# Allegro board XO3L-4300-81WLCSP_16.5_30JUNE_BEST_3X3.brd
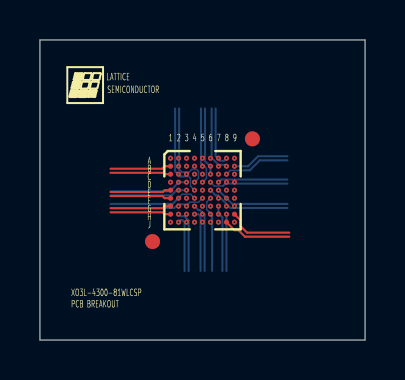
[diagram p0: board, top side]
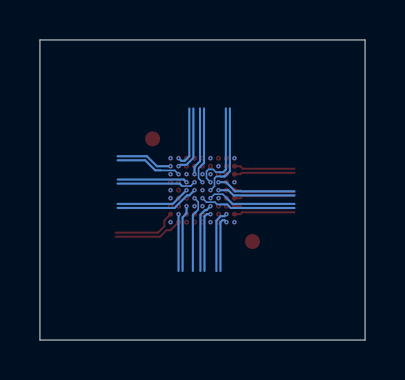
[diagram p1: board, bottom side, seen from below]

Outline 16.28 x 15.02 mm; copper layers: TOP, L2_SIG, L3_PWR/GND, BOTTOM. Coordinates in mm from the lower left corner of the outline.
Outline path: 0,15.02 0,0 16.28,0 16.28,15.02 0,15.02

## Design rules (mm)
net group PB4: nets PB4A PB4B
net group PB7: nets PB7A PB7B
net group PB9: nets PB9A PB9B
net group PB13: nets PB13A PB13B
net group PB15: nets PB15A PB15B
net group PB20: nets PB20A PB20B
net group PB23: nets PB23A PB23B
net group PB24: nets PB24A PB24B
net group PB27: nets PB27A PB27B
net group PB30: nets PB30A PB30B
net group PL4: nets PL4A PL4B
net group PL7: nets PL7A PL7B
net group PL8: nets PL8C PL8D
net group PL15: nets PL15A PL15B
net group PL17: nets PL17A PL17B
net group PL18: nets PL18A PL18B
net group PT9: nets PT9A PT9B
net group PT10: nets PT10A PT10B
net group PT11: nets PT11A PT11B
net group PT13: nets PT13C PT13D
net group PT15: nets PT15C PT15D
net group PT18: nets PT18A PT18B
net group PT19: nets PT19A PT19B
net group PT20: nets PT20C PT20D
net group PT21: nets PT21A PT21B
net group PT22: nets PT22A PT22B
net group PT23: nets PT23C PT23D
net group PT24: nets PT24A PT24B
net group PT25: nets PT25A PT25B
net group PT27: nets PT27A PT27B
net group PT28: nets PT28C PT28D

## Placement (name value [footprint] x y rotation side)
BGA  -  [BGA81N40P9X9_379X369X57B26N]  8.14 7.5 270 top
NOREF  -  []  1.09 11.54 0 top

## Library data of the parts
BGA = BGA81N40P9X9_379X369X57B26N

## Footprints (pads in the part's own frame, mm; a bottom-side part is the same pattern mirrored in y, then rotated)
BGA81N40P9X9_379X369X57B26N
  round 0.75 smd: (-2.57,2.5) (2.57,-2.5)
  round 0.254 smd: A1(-1.6,-1.6) A2(-1.6,-1.2) A3(-1.6,-0.8) A4(-1.6,-0.4) A5(-1.6,0) A6(-1.6,0.4) A7(-1.6,0.8) A8(-1.6,1.2) A9(-1.6,1.6) B1(-1.2,-1.6) B2(-1.2,-1.2) B3(-1.2,-0.8) B4(-1.2,-0.4) B5(-1.2,0) B6(-1.2,0.4) B7(-1.2,0.8) B8(-1.2,1.2) B9(-1.2,1.6) C1(-0.8,-1.6) C2(-0.8,-1.2) C3(-0.8,-0.8) C4(-0.8,-0.4) C5(-0.8,0) C6(-0.8,0.4) C7(-0.8,0.8) C8(-0.8,1.2) C9(-0.8,1.6) D1(-0.4,-1.6) D2(-0.4,-1.2) D3(-0.4,-0.8) D4(-0.4,-0.4) D5(-0.4,0) D6(-0.4,0.4) D7(-0.4,0.8) D8(-0.4,1.2) D9(-0.4,1.6) E1(0,-1.6) E2(0,-1.2) E3(0,-0.8) E4(0,-0.4) E5(0,0) E6(0,0.4) E7(0,0.8) E8(0,1.2) E9(0,1.6) F1(0.4,-1.6) F2(0.4,-1.2) F3(0.4,-0.8) F4(0.4,-0.4) F5(0.4,0) F6(0.4,0.4) F7(0.4,0.8) F8(0.4,1.2) F9(0.4,1.6) G1(0.8,-1.6) G2(0.8,-1.2) G3(0.8,-0.8) G4(0.8,-0.4) G5(0.8,0) G6(0.8,0.4) G7(0.8,0.8) G8(0.8,1.2) G9(0.8,1.6) H1(1.2,-1.6) H2(1.2,-1.2) H3(1.2,-0.8) H4(1.2,-0.4) H5(1.2,0) H6(1.2,0.4) H7(1.2,0.8) H8(1.2,1.2) H9(1.2,1.6) J1(1.6,-1.6) J2(1.6,-1.2) J3(1.6,-0.8) J4(1.6,-0.4) J5(1.6,0) J6(1.6,0.4) J7(1.6,0.8) J8(1.6,1.2) J9(1.6,1.6)

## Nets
GND: BGA.A1 BGA.A9 BGA.E5 BGA.G5 BGA.J1 BGA.J9
VCC: BGA.C4 BGA.D1 BGA.E9 BGA.F3
VCCIO0: BGA.A4 BGA.C5 BGA.C7
VCCIO2: BGA.G6 BGA.J4
VCCIO3: BGA.F9
VCCIO5: BGA.C9
PB4A: BGA.H9
PB4B: BGA.J8
PB7A: BGA.H8
PB7B: BGA.G7
PB9A: BGA.H7
PB9B: BGA.J7
PB13A: BGA.J6
PB13B: BGA.H6
PB15A: BGA.H5
PB15B: BGA.J5
PB20A: BGA.G4
PB20B: BGA.H4
PB23A: BGA.G3
PB23B: BGA.G2
PB24A: BGA.H3
PB24B: BGA.J3
PB27A: BGA.H2
PB27B: BGA.J2
PB30A: BGA.G1
PB30B: BGA.H1
PL4A: BGA.B9
PL4B: BGA.C8
PL5A: BGA.D8
PL7A: BGA.E6
PL7B: BGA.E7
PL8C: BGA.D9
PL8D: BGA.E8
PL15A: BGA.F8
PL15B: BGA.F7
PL16A: BGA.F6
PL17A: BGA.G9
PL17B: BGA.G8
PL18A: BGA.F5
PL18B: BGA.F4
PT9A: BGA.D7
PT9B: BGA.D6
PT10A: BGA.D5
PT10B: BGA.C6
PT11A: BGA.A8
PT11B: BGA.B8
PT13C: BGA.B7
PT13D: BGA.A7
PT15C: BGA.E4
PT15D: BGA.D4
PT18A: BGA.A6
PT18B: BGA.B6
PT19A: BGA.E3
PT19B: BGA.D3
PT20C: BGA.A5
PT20D: BGA.B5
PT21A: BGA.C3
PT21B: BGA.B4
PT22A: BGA.F2
PT22B: BGA.E2
PT23C: BGA.D2
PT23D: BGA.C2
PT24A: BGA.B3
PT24B: BGA.A3
PT25A: BGA.F1
PT25B: BGA.E1
PT27A: BGA.A2
PT27B: BGA.B2
PT28C: BGA.C1
PT28D: BGA.B1

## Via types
v1: diameter 0.2, hole 0.1, TOP to L2_SIG, 32 vias
v2: diameter 0.203, hole 0.102, TOP to BOTTOM, 41 vias

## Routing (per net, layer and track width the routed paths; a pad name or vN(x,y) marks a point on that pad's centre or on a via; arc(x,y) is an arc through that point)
GND:
  vias: v2(6.54,9.1) v2(6.54,5.9) v2(8.14,7.5) v2(8.14,6.7) v2(9.74,9.1) v2(9.74,5.9)
VCC:
  vias: v2(6.54,7.9) v2(7.34,7.1) v2(7.74,8.3) v2(9.74,7.5)
VCCIO0:
  vias: v2(7.74,9.1) v2(8.14,8.3) v2(8.94,8.3)
VCCIO2:
  vias: v2(7.74,5.9) v2(8.54,6.7)
VCCIO3:
  vias: v2(9.74,7.1)
VCCIO5:
  vias: v2(9.74,8.3)
PB4A: length 3.3
  TOP w0.102: BGA.H9 10.05,5.99 10.05,5.69 10.37,5.38 12.49,5.38
PB4B: length 3.4
  TOP w0.102: BGA.J8 9.74,5.5 9.94,5.5 10.26,5.17 12.49,5.17
PB7A: length 2.8
  BOTTOM w0.102: v2(9.34,6.3) 9.34,3.46
PB7B: length 3.3
  BOTTOM w0.102: v2(8.94,6.7) 8.94,6.34 9.14,6.14 9.14,3.46
PB9A: length 3.2
  L2_SIG w0.076: 9.25,5.98 9.14,6.09 9.14,6.1 v1(8.94,6.3)
  L2_SIG w0.102: 9.25,5.98 9.77,5.47 9.77,3.46
PB9B: length 2.7
  L2_SIG w0.102: 9.56,3.46 9.56,5.28 v1(8.94,5.9)
PB13A: length 2.6
  L2_SIG w0.102: 8.87,3.46 8.87,5.14 8.54,5.47 v1(8.54,5.9)
PB13B: length 3.1
  L2_SIG w0.076: v1(8.54,6.3) 8.74,6.1 8.74,5.99 8.74,5.98 8.74,5.72
  L2_SIG w0.102: 9.08,3.46 9.08,5.23 8.74,5.56 8.74,5.72
PB15A: length 2.9
  L2_SIG w0.076: v1(8.14,6.3) 8.34,6.1 8.34,5.49
  L2_SIG w0.102: 8.34,3.46 8.34,5.49
PB15B: length 2.4
  L2_SIG w0.102: v1(8.14,5.9) 8.14,5.58 8.14,5.58 8.14,3.46
PB20A: length 3.5
  BOTTOM w0.102: 8.24,3.46 8.24,6.27 8.01,6.5 7.94,6.5 v2(7.74,6.7)
PB20B: length 3.1
  BOTTOM w0.102: 8.04,3.46 8.04,6.19 7.93,6.3 v2(7.74,6.3)
PB23A: length 4.1
  L2_SIG w0.076: v1(7.34,6.7) 7.14,6.9 6.6,6.9 6.59,6.9 6.52,6.9
  L2_SIG w0.102: 3.54,6.36 5.98,6.36 6.52,6.9
PB23B: length 3.6
  L2_SIG w0.102: v1(6.94,6.7) 6.68,6.7 6.14,6.16 3.54,6.16
PB24A: length 2.9
  L2_SIG w0.076: v1(7.34,6.3) 7.14,6.1 7.14,5.99 7.14,5.98 7.14,5.75
  L2_SIG w0.102: 7.14,3.48 7.14,5.75
PB24B: length 2.4
  L2_SIG w0.102: 7.34,3.48 v1(7.34,5.9)
PB27A: length 3.2
  BOTTOM w0.102: 7.44,3.45 7.44,5.98 7.22,6.2 7.04,6.2 v2(6.94,6.3)
PB27B: length 2.8
  BOTTOM w0.102: 7.24,3.45 7.24,5.9 7.14,6 7.04,6 v2(6.94,5.9)
PB30A: length 3
  TOP w0.102: BGA.G1 6.25,6.7 6.14,6.6 3.54,6.6
PB30B: length 3
  TOP w0.102: BGA.H1 6.25,6.3 6.15,6.39 3.54,6.39
PL4A: length 2.9
  BOTTOM w0.102: v2(9.74,8.7) 10.42,8.7 10.92,9.2 12.39,9.2
PL4B: length 3.3
  BOTTOM w0.076: 10.25,8.5 10.25,8.49 9.53,8.49 v2(9.34,8.3)
  BOTTOM w0.102: 12.39,9 11.01,9 10.51,8.5 10.25,8.5 ; v2(9.34,8.3) 9.34,8.3
PL5A: length 3.1
  L2_SIG w0.076: 12.39,8.1 9.54,8.1 v1(9.34,7.9)
PL7A: length 4.2
  BOTTOM w0.102: 12.39,6.61 9.54,6.61 8.91,7.24 8.8,7.24 v2(8.54,7.5)
PL7B: length 3.7
  BOTTOM w0.102: 12.39,6.81 9.63,6.81 v2(8.94,7.5)
PL8C: length 2.7
  L2_SIG w0.102: 12.39,7.7 10.38,7.7 10.18,7.9 v1(9.74,7.9)
PL8D: length 3.2
  L2_SIG w0.076: 10.16,7.62 10.07,7.7 9.54,7.7 v1(9.34,7.5)
  L2_SIG w0.102: 10.16,7.62 10.27,7.5 12.39,7.5
PL15A: length 3.2
  L2_SIG w0.076: v1(9.34,7.1) 9.35,7.1 9.54,6.91 9.94,6.91
  L2_SIG w0.102: 9.94,6.91 10.02,6.99 12.39,6.99
PL15B: length 3.6
  L2_SIG w0.076: 9.99,7.3 9.14,7.3 v1(8.94,7.1)
  L2_SIG w0.102: 12.39,7.21 10.09,7.21 9.99,7.3
PL16A: length 3.8
  BOTTOM w0.076: 8.47,6.41 8.35,6.53 8.35,6.91 v2(8.54,7.1)
  BOTTOM w0.102: 8.62,3.46 8.62,6.26 8.47,6.41
PL17A: length 2.8
  L2_SIG w0.102: v1(9.74,6.7) 10.21,6.23 12.39,6.23
PL17B: length 3.3
  L2_SIG w0.102: 12.39,6.03 10.13,6.03 9.77,6.38 9.66,6.38 v1(9.34,6.7)
PL18A: length 4.8
  BOTTOM w0.076: v2(8.14,7.1) 7.94,6.9 7.52,6.9 7.4,6.79 7.25,6.79
  BOTTOM w0.102: 3.54,6.61 6.73,6.61 6.9,6.79 7.25,6.79
PL18B: length 4.5
  BOTTOM w0.076: v2(7.74,7.1) 7.54,7.3 7.13,7.3 6.97,7.14
  BOTTOM w0.102: 6.97,7.14 6.64,6.81 3.54,6.81
PT9A: length 3.5
  BOTTOM w0.102: 12.38,8.03 9.07,8.03 v2(8.94,7.9)
PT9B: length 4
  BOTTOM w0.076: 9.19,7.74 9.16,7.71 8.73,7.71 v2(8.54,7.9)
  BOTTOM w0.102: 12.39,7.83 9.28,7.83 9.19,7.74
PT10A: length 3.9
  BOTTOM w0.076: 8.28,8.65 8.34,8.59 8.34,8.1 v2(8.14,7.9)
  BOTTOM w0.102: 8.06,11.59 8.06,8.86 8.28,8.65
PT10B: length 3.4
  BOTTOM w0.102: 8.27,11.59 8.27,8.95 8.54,8.67 8.54,8.39 8.54,8.39 v2(8.54,8.3)
PT11A: length 3.1
  BOTTOM w0.102: 8.8,11.59 8.8,9.2 9.03,8.97 9.21,8.97 v2(9.34,9.1)
PT11B: length 3.4
  BOTTOM w0.102: 8.6,11.59 8.6,9.12 8.94,8.77 9.27,8.77 v2(9.34,8.7)
PT13C: length 3.2
  L2_SIG w0.076: v1(8.94,8.7) 9.14,8.9 9.14,9.31 9.26,9.43
  L2_SIG w0.102: 9.64,11.59 9.64,9.81 9.26,9.43
PT13D: length 2.7
  L2_SIG w0.102: v1(8.94,9.1) 8.94,9.39 9.44,9.89 9.44,11.59
PT15C: length 4.7
  BOTTOM w0.076: v2(7.74,7.5) 7.54,7.7 7.54,8.09 7.45,8.19 7.23,8.19
  BOTTOM w0.102: 6.77,11.59 6.77,8.45 7.02,8.2 7.04,8.2 7.05,8.19 7.23,8.19
PT15D: length 4.8
  BOTTOM w0.076: 7.29,8.4 7.47,8.4 7.61,8.54 7.84,8.54 7.94,8.44 7.94,8.1 v2(7.74,7.9)
  BOTTOM w0.102: 6.97,11.59 6.97,8.53 7.1,8.4 7.29,8.4
PT18A: length 2.7
  L2_SIG w0.076: 8.67,9.86 8.54,9.74 v1(8.54,9.1)
  L2_SIG w0.102: 8.67,9.86 8.94,10.14 8.94,11.59
PT18B: length 3.1
  L2_SIG w0.076: 8.83,9.74 8.74,9.65 8.74,8.9 v1(8.54,8.7)
  L2_SIG w0.102: 9.14,11.59 9.14,10.05 8.83,9.74
PT19A: length 3.9
  BOTTOM w0.102: v2(7.34,7.5) 6.84,7.5 6.59,7.24 3.54,7.24
PT19B: length 4
  BOTTOM w0.102: v2(7.34,7.9) 6.96,7.9 6.5,7.44 3.54,7.44
PT20C: length 2.6
  L2_SIG w0.102: v1(8.14,9.1) 8.14,9.68 7.99,9.84 7.99,11.59
PT20D: length 3
  L2_SIG w0.076: 8.23,9.88 8.34,9.77 8.34,9.02 8.34,9.01 8.34,8.9 v1(8.14,8.7)
  L2_SIG w0.102: 8.23,9.88 8.19,9.92 8.19,11.59
PT21A: length 3.4
  L2_SIG w0.076: 7.43,9.81 7.54,9.71 7.54,8.5 v1(7.34,8.3)
  L2_SIG w0.102: 7.43,9.81 7.35,9.89 7.35,11.59
PT21B: length 3.1
  L2_SIG w0.076: 7.85,9.38 7.94,9.29 7.94,8.9 v1(7.74,8.7)
  L2_SIG w0.102: 7.56,11.59 7.56,9.99 7.74,9.8 7.74,9.49 7.85,9.38
PT22A: length 3.5
  L2_SIG w0.102: 3.54,7.22 6.82,7.22 v1(6.94,7.1)
PT22B: length 3.4
  L2_SIG w0.102: v1(6.94,7.5) 6.86,7.42 3.54,7.42
PT23C: length 3.6
  L2_SIG w0.102: 3.54,8.3 6.48,8.3 6.69,8.08 6.76,8.08 v1(6.94,7.9)
PT23D: length 3.5
  L2_SIG w0.102: 3.54,8.5 6.59,8.5 6.79,8.3 v1(6.94,8.3)
PT24A: length 3.2
  L2_SIG w0.076: 6.87,9.54 7.15,9.26 7.15,8.89 v2(7.34,8.7)
  L2_SIG w0.102: 6.67,11.59 6.67,9.75 6.87,9.54
PT24B: length 2.7
  L2_SIG w0.076: 7.01,9.69 7.03,9.67 7.03,9.67 7.33,9.38 7.33,9.11 v1(7.34,9.1)
  L2_SIG w0.102: 6.87,11.59 6.87,9.83 7.01,9.69
PT25A: length 3
  TOP w0.102: 3.54,7.21 6.14,7.21 6.25,7.1 BGA.F1
PT25B: length 3
  TOP w0.102: BGA.E1 6.25,7.5 6.16,7.41 3.54,7.41
PT27A: length 3.7
  L2_SIG w0.102: 3.54,9.79 5.94,9.79 6.33,9.4 6.64,9.4 v1(6.94,9.1)
PT27B: length 3.8
  L2_SIG w0.102: 3.54,9.58 5.86,9.58 6.23,9.21 6.23,9.07 6.46,8.85 6.79,8.85 v1(6.94,8.7)
PT28C: length 3
  TOP w0.102: 3.54,8.37 6.18,8.37 6.25,8.3 BGA.C1
PT28D: length 3.1
  TOP w0.102: BGA.B1 6.25,8.7 6.12,8.57 3.54,8.57

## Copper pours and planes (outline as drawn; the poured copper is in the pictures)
GND on L3_PWR/GND: 8.39,6.95 8.24,6.8 8.24,6.35 8.09,6.2 7.39,6.2 7.24,6.05 7.24,5.5 6.14,5.5 6.14,9.5 10.25,9.5 10.25,8.2 9.24,8.2 9.24,8.56 8.5,9.3 7.63,9.3 7.48,9.15 7.48,8.55 6.64,8.55 6.34,8.25 6.34,7.22 6.69,6.87 7.43,6.87 7.63,7.07 7.63,7.44 7.79,7.6 9.16,7.6 9.51,7.25 9.51,6.54 10.25,6.54 10.25,5.5 9.04,5.5 9.04,6.8 8.89,6.95
VCC on L3_PWR/GND: 6.69,8.45 7.79,8.45 7.89,8.35 7.89,8.25 8.04,8.1 10.25,8.12 10.25,7.37 9.52,7.37 9.19,7.7 7.74,7.7 7.5,7.47 7.5,7.09 7.37,6.96 6.76,6.96 6.44,7.27 6.44,8.2
VCCIO0 on L3_PWR/GND: 7.66,9.2 7.58,9.13 7.58,8.55 7.84,8.55 7.99,8.4 7.99,8.3 8.09,8.2 9.14,8.2 9.14,8.51 8.45,9.2
VCCIO2 on L3_PWR/GND: 8.34,6.75 8.44,6.85 8.84,6.85 8.94,6.75 8.94,5.5 7.34,5.5 7.34,6 7.44,6.1 8.14,6.1 8.34,6.3

Small or netless copper shapes (teardrops, artwork), in the pictures only: 1 on L3_PWR/GND

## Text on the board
User.Comments: ASP | 06-30-14 | DWG NO: | XO3L-4300-81WLCSP | REVISION | 1.1 | SHEET | 1 | OF | XO3L-4300-81WLCSP PCB BREAKOUT | LATTICE SEMICONDUCTOR CORPORATION
Ref Des/Silkscreen Top: XO3L-4300-81WLCSP | PCB BREAKOUT | LATTICE | SEMICONDUCTOR | A | B | C | D | E | F | G | H | J | 1 | 2 | 3 | 4 | 5 | 6 | 7 | 8 | 9
PAGE_OUTLINE: 149.49 x 145.39 | 15.748 x 15.748 | SPECIAL INSTRUCTIONS: | USE 1/2 OUNCE COPPER FOR BOTH INTERNAL AND EXTERNAL LAYERS | VIAS ARE TO BE NON-CONDUCTIVE EPOXY FILLED | PLANARIZE AT TOP AND BOTTOM | BOARD THICKNESS IS 62MILS | SIGNAL         (L2) | POWER/GND PLANE (L3) | PRIMARY SIDE   (L1) | SECONDARY SIDE (L4) | SECONDARY SILKSCREEN | SECONDARY SOLDERMASK | PRIMARY SOLDERMASK | PRIMARY SILKSCREEN | DESIGNED BY: | APPROVED BY: | SIGNATURES         DATE | REV | 1 | INITIAL RELEASE | ESCAPE VIA DRILL | TRACE WIDTH/SPACE | ESCAPE VIA PAD | ARRAY SIZE | BGA LAND OPENING | BGA LAND PAD | PACKAGE SIZE | PITCH | DESCRIPTION | 3.797x3.693 | 0.0762 | 0.254 | 0.2032 | 0.1016 | 9 X 9 | 0.40 | MM | MM/DD/YYYY | DATE | 15.748 | 10.00 | 3/3.0 | 8.00 | MILS | 4.00 | APPROVED | XXXXXXXXX | 4 LAYER STACKUP | PCB BREAKOUT DETAILS | REVISION
PLACE_BOUND_TOP: FIGURE | SIZE | 0.1 | ALL UNITS ARE IN MILLIMETERS | SIZE MM | PLATED | QTY | 22 | DRILL CHART: TOP to L4_IO
DISPLAY_TOP: FIGURE | SIZE | 0.1 | ALL UNITS ARE IN MILLIMETERS | SIZE MM | PLATED | QTY | 26 | DRILL CHART: TOP to BOTTOM
DEVICE_TYPE_TOP: FIGURE | SIZE | 0.1 | ALL UNITS ARE IN MILLIMETERS | SIZE MM | PLATED | QTY | 25 | DRILL CHART: TOP to L3_IO
